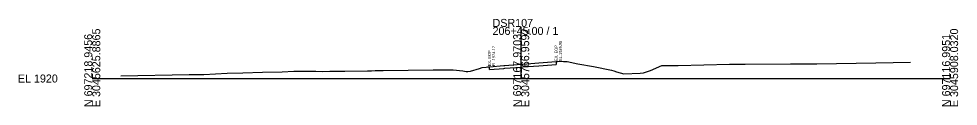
# Model space of a CAD drawing. Extents: x -26 to 19003, y -31 to 24541.
# Drawn here: x 1974.3 to 2302.8, y 11990.3 to 12020.9 of the extents above; entities that cross this region are included whole.
import ezdxf

# ---------------------------------------------------------------- set-up
doc = ezdxf.new("R2010")
doc.units = 0
for name, color, linetype in [('DESIGN - SHEET - Light Grid', 7, 'Continuous'), ('SURVEY - GROUND - Existing Pavement Layer', 7, 'Continuous'), ('SURVEY - GROUND - Existing Pavement Text', 7, 'Continuous'), ('SURVEY - GROUND - Top of Ground', 7, 'Continuous')]:
    doc.layers.add(name, color=color, linetype=linetype)

msp = doc.modelspace()

# ---------------------------------------------------------------- linework, layer by layer
at = {"layer": 'DESIGN - SHEET - Light Grid'}
for p, q in [((2150, 12000), (2150, 12018.05)), ((2000, 12000), (2150, 12000)), ((2150, 12000), (2300, 12000))]:
    msp.add_line(p, q, dxfattribs=at)
at = {"layer": 'SURVEY - GROUND - Existing Pavement Layer'}
for p, q in [((2156.13, 12004.47), (2162.22, 12004.95)), ((2162.22, 12005.95), (2162.22, 12004.95)), ((2138.9, 12003.12), (2138.9, 12004.12)), ((2138.9, 12003.12), (2143.92, 12003.51)), ((2143.92, 12003.51), (2144.33, 12003.56)), ((2144.33, 12003.56), (2150, 12003.99)), ((2150, 12003.99), (2150.61, 12004.04)), ((2150.61, 12004.04), (2156.13, 12004.47))]:
    msp.add_line(p, q, dxfattribs=at)
at = {"layer": 'SURVEY - GROUND - Top of Ground'}
msp.add_lwpolyline([(2009.97, 12000.88), (2033.91, 12001.36), (2038.99, 12001.46), (2047.16, 12001.82), (2052.64, 12001.97), (2059.58, 12002.24), (2066.42, 12002.39), (2070.51, 12002.53), (2078.23, 12002.52), (2080.57, 12002.49), (2083.07, 12002.53), (2083.99, 12002.54), (2084.48, 12002.55), (2088.32, 12002.6), (2096.26, 12002.7), (2097.65, 12002.73), (2098.89, 12002.76), (2101.73, 12002.78), (2119.28, 12003.05), (2120.63, 12003.03), (2126.27, 12003.07), (2129.59, 12002.72), (2130.71, 12002.5), (2131.37, 12002.51), (2132.32, 12002.54), (2135.41, 12003.52), (2136.34, 12003.85), (2137.81, 12004), (2138.2, 12004.05), (2138.9, 12004.12), (2143.92, 12004.51), (2144.33, 12004.56), (2150, 12004.99), (2150.61, 12005.04), (2156.13, 12005.47), (2162.22, 12005.95), (2162.75, 12005.99), (2163.34, 12006.02), (2164.75, 12005.98), (2166.08, 12005.97), (2169.86, 12005.16), (2175.25, 12004.16), (2181.61, 12002.94), (2182.38, 12002.67), (2183.3, 12002.39), (2185.87, 12001.67), (2191.66, 12001.9), (2192.83, 12001.97), (2195.18, 12002.77), (2199.19, 12004.51), (2204.95, 12004.59), (2222.85, 12004.97), (2228.36, 12005.02), (2244.18, 12005.13), (2253.41, 12005.09), (2274.04, 12005.47), (2286.2, 12005.76)], dxfattribs=at)

# ---------------------------------------------------------------- texts
at = {"layer": 'DESIGN - SHEET - Light Grid'}
for s, p in [('206+45.00 / 1', (2140, 12015.25)), ('DSR107', (2140, 12018.05)), ('EL 1920', (1974, 11998.6))]:
    msp.add_text(s, height=2.8, dxfattribs=at).set_placement(p)
for s, p in [('N 697218.9456', (2000, 11990)), ('E 3045625.8865', (2002.8, 11990)), ('N 697167.9703', (2150, 11990)), ('E 3045766.9592', (2152.8, 11990)), ('N 697116.9951', (2300, 11990)), ('E 3045908.0320', (2302.8, 11990))]:
    msp.add_text(s, height=2.8, rotation=90, dxfattribs=at).set_placement(p)
at = {"layer": 'SURVEY - GROUND - Existing Pavement Text'}
for s, p in [('EX. EOP', (2162.72, 12006.15)), ('EL.1925.95', (2164.22, 12006.15)), ('EX. EOP', (2139.4, 12004.32)), ('EL.1924.12', (2140.9, 12004.32))]:
    msp.add_text(s, height=1, rotation=90, dxfattribs=at).set_placement(p)

doc.saveas('drawing.dxf')
